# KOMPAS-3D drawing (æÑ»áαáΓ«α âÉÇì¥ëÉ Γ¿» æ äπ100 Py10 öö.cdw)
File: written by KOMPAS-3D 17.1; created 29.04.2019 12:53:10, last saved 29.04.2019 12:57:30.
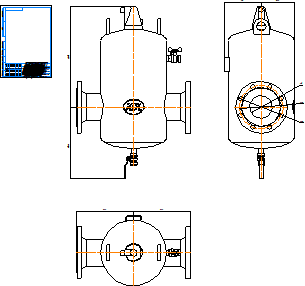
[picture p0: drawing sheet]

Sheet 1: A4, portrait

Title block, sheet 1: name: Сепаратор ГРАНЭЙР тип С / Ду100 Py10 ФФ; material: Внимание! Данный продукт является объектом авторского права ООО «Торговый Дом АДЛ». / Запрещается изменение, копирование, распространение / (в том числе путем копирования на другие сайты и ресурсы в Интернете) / или любое иное использование информации и объектов без предварительного / согласия правообладателя (ООО «Торговый Дом АДЛ»).; sheets: 1; organisation: ООО "Торговый дом АДЛ"; sheet format: A4

Views: Вид 1, Проекционный вид 2, Проекционный вид 3
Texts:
  user
Dimensions and other numbers on the sheet: 292,68; 412,89; 235; 153; 136,5; 96; 180; 215; 1:1; 1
